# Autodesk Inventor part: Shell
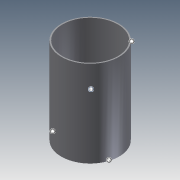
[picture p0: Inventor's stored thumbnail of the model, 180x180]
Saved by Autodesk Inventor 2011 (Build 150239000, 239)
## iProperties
Created: 2010-06
Part Number: Shell
Document SubType Name: Modeling
Designer: mklassen
Density: 1 g/cm^3
OD: 24.000 in
THK: 0.500 in
LEN: 3.000 ft
SKVOFS: 6.000 in
Author: mklassen
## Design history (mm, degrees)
sketch "skShell"
  geometry: C1 r 304.8 at (0, 0); C2 r 292.1 at (0, 0); 1 further point
  constraints: 2 centre point, 1 coincident
  dimensions: "d0" = 609.6 diameter of C1 (derived); "d1" = 12.7 radial gap between concentric circles of C2 C1 (derived)
extrude "Shell" new body sketch "skShell" stored distance "d2" = 914.4 (derived); taper "d3" = 0 deg
body "Solid1"
other parameters: "d4" = 0, "d5" = 0, "d6" = 0, "d7" = 0, "d8" = 0, "SKVOFS" = 152.4 [user parameter], "d9" = 0
